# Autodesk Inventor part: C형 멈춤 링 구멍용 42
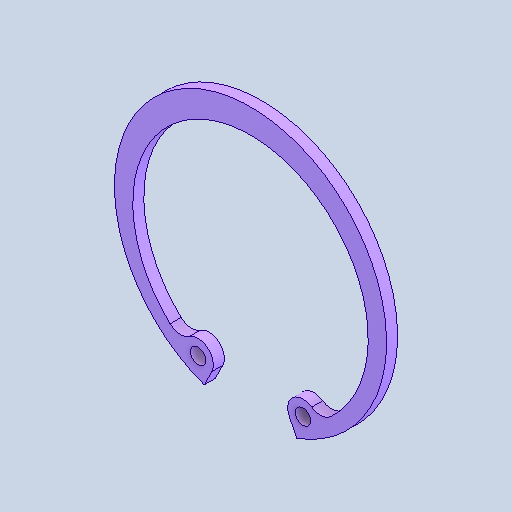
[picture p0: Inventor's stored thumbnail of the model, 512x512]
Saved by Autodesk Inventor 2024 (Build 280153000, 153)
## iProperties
Created: 2025-11
Part Number: C형 멈춤 링 구멍용 42
Material: 강철, 연강
Description: 리테이닝 링(C형)
Document SubType Name: Modeling
Designer: Edu07
Density: 7.85 g/cm^3
Appearance: 기본값
Author: jhkim
Sending System: Autodesk Inventor 2026
Preprocessor: ST-DEVELOPER v20.1
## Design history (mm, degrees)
node "C형 멈춤링 구멍용 421"
node "솔리드1"
body "Solid1"
